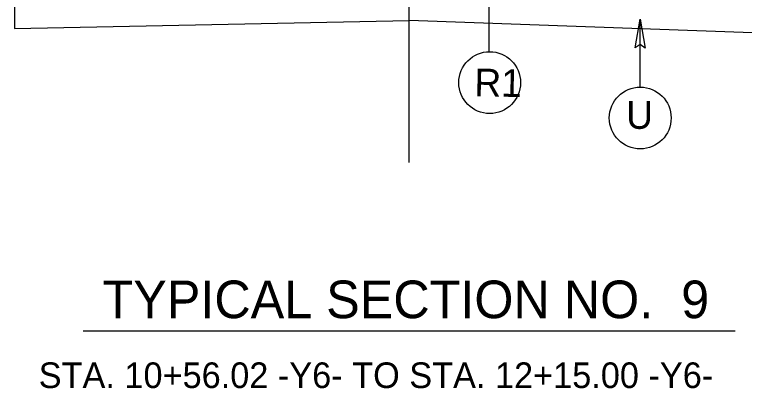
# Model space of a CAD drawing. Extents: x 2176156 to 2177167, y 76401 to 76644.
# Drawn here: x 2176819.16 to 2176849.74, y 76400.57 to 76416.24 of the extents above; entities that cross this region are included whole.
import ezdxf

# ---------------------------------------------------------------- set-up
doc = ezdxf.new("R2010")
doc.units = 0
for name, color, linetype in [('Exist Building Metal Canopy', 7, 'Continuous'), ('Exist Vegetation Woods Line', 7, 'Continuous'), ('Model Boundary Lines Text', 7, 'Continuous'), ('Old_Level_3', 7, 'Continuous'), ('Prop North Arrow NAD83 for Plan Sheets CELL', 7, 'Continuous'), ('Sheet Plan CELL', 7, 'Continuous')]:
    doc.layers.add(name, color=color, linetype=linetype)

msp = doc.modelspace()

# ---------------------------------------------------------------- linework, layer by layer
at = {"layer": 'Model Boundary Lines Text'}
msp.add_line((2176822.031, 76402.987), (2176849.352, 76402.987), dxfattribs=at)
at = {"layer": 'Old_Level_3'}
msp.add_line((2176835.691, 76410.033), (2176835.691, 76429.049), dxfattribs=at)
at = {"layer": 'Prop North Arrow NAD83 for Plan Sheets CELL'}
for p, q in [((2176839.043, 76414.681), (2176839.043, 76418.446)), ((2176845.377, 76413.199), (2176845.377, 76416.041))]:
    msp.add_line(p, q, dxfattribs=at)
msp.add_lwpolyline([(2176845.17, 76414.841), (2176845.377, 76416.041), (2176845.59, 76414.835), (2176845.377, 76414.988)], close=True, dxfattribs=at)
for centre in [(2176839.069, 76413.385), (2176845.377, 76411.903)]:
    msp.add_circle(centre, 1.296, dxfattribs=at)
at = {"layer": 'Sheet Plan CELL'}
for p, q in [((2176819.161, 76417.476), (2176819.161, 76415.65)), ((2176819.161, 76415.65), (2176835.691, 76415.992)), ((2176860.366, 76415.098), (2176835.691, 76415.992))]:
    msp.add_line(p, q, dxfattribs=at)

# ---------------------------------------------------------------- texts
at = {"layer": 'Exist Building Metal Canopy'}
msp.add_text('TYPICAL SECTION NO.  9', height=1.5766, rotation=0, dxfattribs=at).set_placement((2176822.845, 76403.515))
at = {"layer": 'Exist Vegetation Woods Line'}
msp.add_text('STA. 10+56.02 -Y6- TO STA. 12+15.00 -Y6-', height=1.0742, dxfattribs=at).set_placement((2176820.172, 76400.588))
at = {"layer": 'Prop North Arrow NAD83 for Plan Sheets CELL'}
for s, rotation, p in [('R1', 358.8249, (2176838.421, 76412.819)), ('U', 0.0003, (2176844.79, 76411.449))]:
    msp.add_text(s, height=1.16, rotation=rotation, dxfattribs=at).set_placement(p)

doc.saveas('drawing.dxf')
